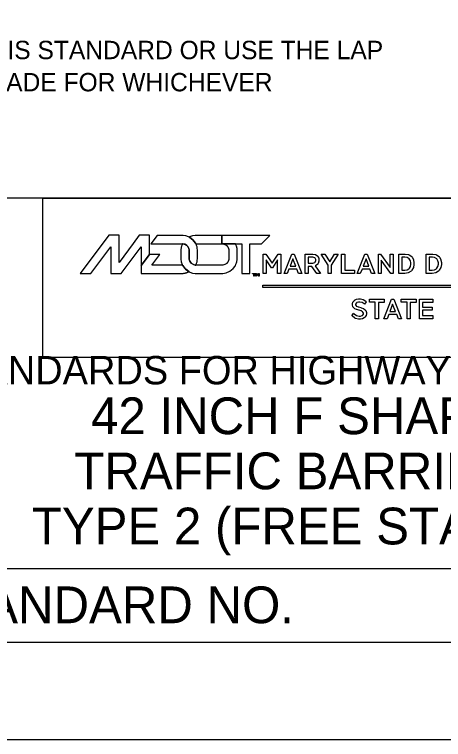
# Model space of a CAD drawing. Extents: x -27.4 to -18.9, y -4.2 to 6.8.
# Drawn here: x -23.046 to -21.647, y -4.191 to -1.823 of the extents above; entities that cross this region are included whole.
import ezdxf

# ---------------------------------------------------------------- set-up
doc = ezdxf.new("R2010")
doc.units = 0
for name, color, linetype in [('BORD-LINE', 7, 'Continuous'), ('Level 13', 7, 'Continuous'), ('MSHA-LOGO', 7, 'Continuous'), ('TTLB-TEXT', 7, 'Continuous'), ('USER-CLIP', 7, 'Continuous'), ('USER-LINE', 7, 'Continuous')]:
    doc.layers.add(name, color=color, linetype=linetype)

msp = doc.modelspace()

# ---------------------------------------------------------------- linework, layer by layer
at = {"layer": 'BORD-LINE'}
for p, q in [((-19.2324, -2.4232), (-23.7053, -2.4232)), ((-23.7053, -3.6322), (-19.2324, -3.6322))]:
    msp.add_line(p, q, dxfattribs=at)
msp.add_lwpolyline([(-26.6066, 6.4791), (-19.2324, 6.4791), (-19.2324, -3.874), (-26.6066, -3.874)], close=True, dxfattribs=at)
at = {"layer": 'MSHA-LOGO'}
for points in [[(-22.6334, -2.6432), (-22.6062, -2.607), (-22.6062, -2.5443), (-22.6392, -2.5443), (-22.6596, -2.5717), (-22.7055, -2.6329), (-22.7055, -2.5443), (-22.7384, -2.5443), (-22.8317, -2.6687), (-22.7977, -2.6687), (-22.7326, -2.5819), (-22.7326, -2.6687), (-22.6984, -2.6687), (-22.6334, -2.5819)], [(-22.4982, -2.5722), (-22.4974, -2.5723), (-22.4898, -2.5743), (-22.4891, -2.5747), (-22.4883, -2.5751), (-22.4845, -2.5778), (-22.4813, -2.5812), (-22.4807, -2.5819), (-22.4801, -2.5827), (-22.4779, -2.5874), (-22.4767, -2.5925), (-22.4766, -2.5936), (-22.4766, -2.5936), (-22.4766, -2.5938), (-22.4766, -2.5938), (-22.4766, -2.594), (-22.4766, -2.5946), (-22.4766, -2.5948), (-22.4766, -2.6184), (-22.4766, -2.6186), (-22.4766, -2.6192), (-22.4766, -2.6194), (-22.4766, -2.6194), (-22.4766, -2.6196), (-22.4766, -2.6196), (-22.4766, -2.6201), (-22.4768, -2.6213), (-22.4768, -2.6217), (-22.4765, -2.6236), (-22.4743, -2.6293), (-22.4696, -2.6355), (-22.4628, -2.64), (-22.4567, -2.6419), (-22.4554, -2.6419), (-22.4551, -2.6416), (-22.455, -2.6413), (-22.455, -2.6413), (-22.4548, -2.6409), (-22.4527, -2.6364), (-22.4526, -2.636), (-22.4524, -2.6355), (-22.451, -2.6308), (-22.4508, -2.6303), (-22.4508, -2.63), (-22.4502, -2.6276), (-22.4502, -2.6274), (-22.45, -2.6266), (-22.4493, -2.6203), (-22.4493, -2.6182), (-22.4493, -2.5951), (-22.4493, -2.5929), (-22.45, -2.5868), (-22.4502, -2.586), (-22.4502, -2.5858), (-22.4508, -2.5833), (-22.4508, -2.5831), (-22.451, -2.5826), (-22.4524, -2.5779), (-22.4526, -2.5774), (-22.4527, -2.5769), (-22.4548, -2.5725), (-22.455, -2.5721), (-22.4562, -2.5697), (-22.4641, -2.5595), (-22.4743, -2.5516), (-22.4766, -2.5504), (-22.4783, -2.5495), (-22.4875, -2.5463), (-22.4965, -2.5449), (-22.4994, -2.5449), (-22.5813, -2.5449), (-22.6018, -2.5721), (-22.4994, -2.5721), (-22.4994, -2.5721), (-22.4985, -2.5722)], [(-22.4548, -2.5724), (-22.4544, -2.5724), (-22.4541, -2.5724), (-22.3702, -2.5724), (-22.37, -2.5724), (-22.3697, -2.5724), (-22.3696, -2.5724), (-22.3695, -2.5721), (-22.3695, -2.545), (-22.3695, -2.545), (-22.37, -2.545), (-22.3702, -2.545), (-22.4541, -2.545), (-22.4571, -2.545), (-22.4661, -2.5465), (-22.4752, -2.5497), (-22.4766, -2.5504), (-22.4743, -2.5516), (-22.4641, -2.5595), (-22.4562, -2.5697), (-22.455, -2.5721)], [(-22.3695, -2.545), (-22.3695, -2.5722), (-22.3051, -2.5722), (-22.3051, -2.6687), (-22.2781, -2.6687), (-22.2781, -2.5722), (-22.2405, -2.5722), (-22.2136, -2.5452), (-22.2136, -2.545)], [(-22.4761, -2.6632), (-22.4762, -2.6632), (-22.4764, -2.663), (-22.4764, -2.663), (-22.4776, -2.6624), (-22.4879, -2.6548), (-22.4888, -2.6539), (-22.4897, -2.653), (-22.4971, -2.6428), (-22.4977, -2.6416), (-22.4979, -2.6416), (-22.4982, -2.6416), (-22.4982, -2.6416), (-22.4985, -2.6416), (-22.4992, -2.6416), (-22.4994, -2.6416), (-22.5989, -2.6416), (-22.5724, -2.6067), (-22.6064, -2.6067), (-22.6335, -2.6427), (-22.6335, -2.6689), (-22.4996, -2.6689), (-22.4988, -2.6689), (-22.4968, -2.6687), (-22.4965, -2.6687), (-22.4958, -2.6687), (-22.4939, -2.6684), (-22.4936, -2.6683), (-22.4934, -2.6683), (-22.4929, -2.6682), (-22.4927, -2.6682), (-22.4926, -2.6681), (-22.491, -2.6679), (-22.4909, -2.6678), (-22.4906, -2.6678), (-22.49, -2.6676), (-22.4898, -2.6676), (-22.4897, -2.6676), (-22.4882, -2.6673), (-22.4881, -2.6673), (-22.488, -2.6673), (-22.4872, -2.667), (-22.4871, -2.667), (-22.487, -2.6669), (-22.4857, -2.6665), (-22.4855, -2.6664), (-22.4855, -2.6664), (-22.4846, -2.6661), (-22.4845, -2.6661), (-22.4844, -2.6661), (-22.4831, -2.6656), (-22.483, -2.6656), (-22.4829, -2.6655), (-22.482, -2.6653), (-22.4819, -2.6652), (-22.4818, -2.6652), (-22.4803, -2.6646), (-22.4802, -2.6645), (-22.4801, -2.6645), (-22.4794, -2.6642), (-22.4794, -2.6642), (-22.4791, -2.6641), (-22.4771, -2.6631), (-22.477, -2.663), (-22.4768, -2.6631), (-22.4763, -2.6632)], [(-22.2353, -2.6056), (-22.2265, -2.6056), (-22.2062, -2.6352), (-22.1865, -2.6056), (-22.178, -2.6056), (-22.178, -2.669), (-22.1879, -2.669), (-22.1879, -2.625), (-22.2052, -2.6503), (-22.2078, -2.6503), (-22.2255, -2.625), (-22.2255, -2.669), (-22.2353, -2.669)], [(-22.1417, -2.6056), (-22.1342, -2.6056), (-22.1093, -2.669), (-22.1198, -2.669), (-22.1253, -2.6549), (-22.1512, -2.6549), (-22.1568, -2.669), (-22.1669, -2.669)], [(-22.1473, -2.6457), (-22.1286, -2.6457), (-22.1381, -2.6217)], [(-22.0979, -2.6694), (-22.0979, -2.6059), (-22.0756, -2.6059), (-22.0728, -2.6059), (-22.0653, -2.6073), (-22.0645, -2.6075), (-22.0637, -2.6078), (-22.058, -2.6116), (-22.0576, -2.6121), (-22.0572, -2.6126), (-22.0543, -2.6178), (-22.054, -2.6184), (-22.0538, -2.619), (-22.053, -2.6242), (-22.053, -2.6259), (-22.053, -2.6288), (-22.0557, -2.6366), (-22.0563, -2.6375), (-22.0569, -2.6383), (-22.0645, -2.644), (-22.0655, -2.6444), (-22.0484, -2.6697), (-22.0605, -2.6697), (-22.0759, -2.6463), (-22.088, -2.6463), (-22.088, -2.6697), (-22.0979, -2.6697)], [(-22.088, -2.6161), (-22.088, -2.6355), (-22.0753, -2.6355), (-22.0731, -2.6355), (-22.067, -2.6333), (-22.0664, -2.6328), (-22.0659, -2.6324), (-22.0632, -2.6271), (-22.0632, -2.6253), (-22.0632, -2.6236), (-22.0656, -2.6188), (-22.0661, -2.6184), (-22.0666, -2.618), (-22.0733, -2.6161), (-22.0756, -2.6161)], [(-22.0131, -2.6417), (-22.0131, -2.6694), (-22.0229, -2.6694), (-22.0229, -2.6417), (-22.0458, -2.6056), (-22.0337, -2.6056), (-22.018, -2.6309), (-22.002, -2.6056), (-21.9902, -2.6056)], [(-21.9791, -2.6056), (-21.9692, -2.6056), (-21.9692, -2.6588), (-21.9368, -2.6588), (-21.9368, -2.669), (-21.9791, -2.669)], [(-21.9031, -2.6056), (-21.8956, -2.6056), (-21.8707, -2.669), (-21.8812, -2.669), (-21.8868, -2.6549), (-21.9126, -2.6549), (-21.9182, -2.669), (-21.928, -2.669)], [(-21.9087, -2.6457), (-21.8901, -2.6457), (-21.8995, -2.6217)], [(-21.8184, -2.6694), (-21.8498, -2.6259), (-21.8498, -2.6694), (-21.8593, -2.6694), (-21.8593, -2.6059), (-21.8518, -2.6059), (-21.8203, -2.6493), (-21.8203, -2.6059), (-21.8108, -2.6059), (-21.8108, -2.6694)], [(-21.7928, -2.6056), (-21.7752, -2.6056), (-21.7714, -2.6056), (-21.7612, -2.6074), (-21.7601, -2.6078), (-21.7591, -2.6083), (-21.7506, -2.614), (-21.75, -2.6148), (-21.7494, -2.6155), (-21.745, -2.6237), (-21.7447, -2.6246), (-21.7445, -2.6255), (-21.7431, -2.6337), (-21.7431, -2.6365), (-21.7431, -2.6397), (-21.7451, -2.6495), (-21.7499, -2.6586), (-21.7513, -2.6602), (-21.7527, -2.6616), (-21.7616, -2.6668), (-21.7725, -2.669), (-21.7762, -2.669), (-21.7928, -2.669)], [(-21.783, -2.6161), (-21.783, -2.6588), (-21.7755, -2.6588), (-21.7731, -2.6588), (-21.7657, -2.6574), (-21.7597, -2.6539), (-21.7588, -2.6529), (-21.7579, -2.6519), (-21.7547, -2.6458), (-21.7533, -2.6388), (-21.7533, -2.6365), (-21.7533, -2.6342), (-21.7546, -2.6274), (-21.7587, -2.6209), (-21.7656, -2.617), (-21.7728, -2.6157), (-21.7752, -2.6157), (-21.783, -2.6157)], [(-21.7035, -2.6056), (-21.6858, -2.6056), (-21.6821, -2.6056), (-21.6719, -2.6074), (-21.6708, -2.6078), (-21.6697, -2.6083), (-21.6613, -2.614), (-21.6607, -2.6148), (-21.6601, -2.6155), (-21.6557, -2.6237), (-21.6554, -2.6246), (-21.6552, -2.6255), (-21.6538, -2.6337), (-21.6538, -2.6365), (-21.6538, -2.6397), (-21.6558, -2.6495), (-21.6606, -2.6586), (-21.6619, -2.6602), (-21.6633, -2.6616), (-21.6723, -2.6668), (-21.6832, -2.669), (-21.6868, -2.669), (-21.7035, -2.669)], [(-21.6934, -2.6161), (-21.6934, -2.6588), (-21.6858, -2.6588), (-21.6834, -2.6588), (-21.676, -2.6574), (-21.6701, -2.6539), (-21.6692, -2.6529), (-21.6683, -2.6519), (-21.665, -2.6458), (-21.6636, -2.6388), (-21.6636, -2.6365), (-21.6636, -2.6342), (-21.6649, -2.6274), (-21.669, -2.6209), (-21.6759, -2.617), (-21.6831, -2.6157), (-21.6855, -2.6157), (-21.6934, -2.6157)], [(-22.2695, -2.6687), (-22.2606, -2.6687), (-22.2606, -2.6703), (-22.2641, -2.6703), (-22.2641, -2.6776), (-22.2659, -2.6776), (-22.2659, -2.6703), (-22.2695, -2.6703)], [(-22.2594, -2.6687), (-22.2578, -2.6687), (-22.2539, -2.6731), (-22.2503, -2.6687), (-22.2487, -2.6687), (-22.2487, -2.6776), (-22.2507, -2.6776), (-22.2507, -2.6712), (-22.2541, -2.6753), (-22.2576, -2.6712), (-22.2576, -2.6776), (-22.2594, -2.6776)], [(-22.2362, -2.7073), (-20.1195, -2.7073), (-20.1195, -2.7152), (-22.2362, -2.7152)], [(-21.9101, -2.7946), (-21.9105, -2.7943), (-21.9147, -2.7916), (-21.9152, -2.7914), (-21.9158, -2.7912), (-21.9216, -2.7893), (-21.9223, -2.7891), (-21.9229, -2.789), (-21.9293, -2.7871), (-21.9299, -2.7869), (-21.9306, -2.7866), (-21.9364, -2.784), (-21.937, -2.7837), (-21.9375, -2.7833), (-21.9418, -2.7788), (-21.9421, -2.7782), (-21.9424, -2.7776), (-21.944, -2.7718), (-21.944, -2.7699), (-21.944, -2.7681), (-21.9424, -2.7628), (-21.9387, -2.7579), (-21.9376, -2.757), (-21.9366, -2.7561), (-21.9304, -2.7531), (-21.9236, -2.7519), (-21.9213, -2.7519), (-21.9181, -2.7519), (-21.9086, -2.7542), (-21.9003, -2.7597), (-21.899, -2.7612), (-21.9044, -2.7692), (-21.9056, -2.7681), (-21.9123, -2.7642), (-21.9193, -2.7625), (-21.9216, -2.7625), (-21.9238, -2.7625), (-21.9297, -2.7641), (-21.9303, -2.7644), (-21.9308, -2.7647), (-21.9338, -2.7688), (-21.9338, -2.7702), (-21.9338, -2.7715), (-21.9316, -2.7749), (-21.9312, -2.7753), (-21.9308, -2.7756), (-21.9252, -2.778), (-21.9245, -2.7782), (-21.9238, -2.7784), (-21.9167, -2.7805), (-21.9159, -2.7808), (-21.9151, -2.781), (-21.9079, -2.7837), (-21.9073, -2.784), (-21.9066, -2.7843), (-21.901, -2.7891), (-21.9005, -2.7898), (-21.9001, -2.7904), (-21.898, -2.7969), (-21.898, -2.7991), (-21.898, -2.801), (-21.8996, -2.8067), (-21.9033, -2.812), (-21.9044, -2.8129), (-21.9054, -2.8138), (-21.9115, -2.8169), (-21.9179, -2.8183), (-21.92, -2.8183), (-21.9237, -2.8183), (-21.9335, -2.8157), (-21.9347, -2.8151), (-21.9359, -2.8146), (-21.945, -2.8076), (-21.9456, -2.8068), (-21.9395, -2.7991), (-21.9383, -2.8006), (-21.9306, -2.806), (-21.922, -2.8084), (-21.9191, -2.8084), (-21.9171, -2.8084), (-21.9116, -2.8068), (-21.9111, -2.8065), (-21.9106, -2.8061), (-21.9082, -2.802), (-21.9082, -2.8007), (-21.9082, -2.7992), (-21.9098, -2.7949)], [(-21.8887, -2.7528), (-21.8402, -2.7528), (-21.8402, -2.7634), (-21.8593, -2.7634), (-21.8593, -2.8171), (-21.8692, -2.8171), (-21.8692, -2.7631), (-21.8884, -2.7631), (-21.8884, -2.7528)], [(-21.8162, -2.7528), (-21.8085, -2.7528), (-21.7833, -2.8171), (-21.7938, -2.8171), (-21.7993, -2.8029), (-21.8255, -2.8029), (-21.8309, -2.8171), (-21.8411, -2.8171)], [(-21.822, -2.7933), (-21.8031, -2.7933), (-21.8127, -2.7689)], [(-21.7849, -2.7528), (-21.7363, -2.7528), (-21.7363, -2.7634), (-21.7555, -2.7634), (-21.7555, -2.8171), (-21.7654, -2.8171), (-21.7654, -2.7631), (-21.7846, -2.7631), (-21.7846, -2.7528)], [(-21.7248, -2.7528), (-21.682, -2.7528), (-21.682, -2.7634), (-21.7149, -2.7634), (-21.7149, -2.7795), (-21.6842, -2.7795), (-21.6842, -2.7894), (-21.7149, -2.7894), (-21.7149, -2.8065), (-21.6814, -2.8065), (-21.6814, -2.8171), (-21.7248, -2.8171)]]:
    msp.add_lwpolyline(points, close=True, dxfattribs=at)
for points in [[(-22.4766, -2.6081), (-22.4766, -2.5951), (-22.4766, -2.5948), (-22.4766, -2.594), (-22.4766, -2.5938), (-22.4766, -2.5933), (-22.4764, -2.5921), (-22.4764, -2.5917), (-22.4766, -2.5908), (-22.4799, -2.5824), (-22.4804, -2.5817), (-22.4809, -2.5809), (-22.4842, -2.5775), (-22.4881, -2.5747), (-22.489, -2.5743), (-22.4897, -2.5739), (-22.4973, -2.5719), (-22.4981, -2.5719), (-22.4981, -2.572), (-22.4982, -2.5722), (-22.4986, -2.5729), (-22.5013, -2.5796), (-22.5015, -2.5803), (-22.5016, -2.5806), (-22.5023, -2.583), (-22.5024, -2.5833), (-22.5026, -2.5842), (-22.5037, -2.5924), (-22.5037, -2.5951), (-22.5037, -2.6081), (-22.5037, -2.6094)], [(-22.3199, -2.5951), (-22.3199, -2.5944), (-22.32, -2.5925), (-22.32, -2.5922), (-22.32, -2.5921), (-22.32, -2.5914), (-22.32, -2.5908), (-22.3202, -2.5897), (-22.3202, -2.5893), (-22.3202, -2.5892), (-22.3202, -2.5889), (-22.3202, -2.5888), (-22.3202, -2.5887), (-22.3202, -2.5885), (-22.3202, -2.5884), (-22.3202, -2.5883), (-22.3205, -2.5865), (-22.3205, -2.5864), (-22.3205, -2.5862), (-22.3207, -2.5858), (-22.3207, -2.5857), (-22.3208, -2.5855), (-22.3212, -2.5836), (-22.3212, -2.5834), (-22.3212, -2.5833), (-22.3212, -2.5831), (-22.3213, -2.5828), (-22.322, -2.5802), (-22.3221, -2.58), (-22.3222, -2.5796), (-22.3238, -2.5753), (-22.324, -2.5748), (-22.3241, -2.5746), (-22.3251, -2.5725), (-22.3252, -2.5722), (-22.3252, -2.5722), (-22.3253, -2.5719), (-22.3688, -2.5719), (-22.369, -2.5722), (-22.3684, -2.5722), (-22.3683, -2.5722), (-22.368, -2.5722), (-22.3675, -2.5724), (-22.3674, -2.5724), (-22.3671, -2.5725), (-22.3636, -2.5731), (-22.3633, -2.5733), (-22.363, -2.5734), (-22.3602, -2.5743), (-22.3598, -2.5745), (-22.3597, -2.5746), (-22.3581, -2.5754), (-22.358, -2.5755), (-22.3578, -2.5755), (-22.3578, -2.5755), (-22.3577, -2.5756), (-22.3562, -2.5765), (-22.3561, -2.5766), (-22.3559, -2.5767), (-22.3559, -2.5767), (-22.3558, -2.5768), (-22.3545, -2.5778), (-22.3544, -2.5779), (-22.3542, -2.5781), (-22.3541, -2.5782), (-22.3531, -2.5792), (-22.353, -2.5793), (-22.3529, -2.5795), (-22.3528, -2.5795), (-22.3526, -2.5796), (-22.3526, -2.5797), (-22.3518, -2.5806), (-22.3518, -2.5807), (-22.3516, -2.5809), (-22.3516, -2.5809), (-22.3513, -2.5813), (-22.3513, -2.5814), (-22.3512, -2.5815), (-22.3505, -2.5825), (-22.3504, -2.5826), (-22.3504, -2.5826), (-22.3501, -2.5832), (-22.3501, -2.5833), (-22.3499, -2.5834), (-22.3499, -2.5834), (-22.3499, -2.5835), (-22.3494, -2.5844), (-22.3494, -2.5845), (-22.3493, -2.5846), (-22.3491, -2.5852), (-22.349, -2.5853), (-22.349, -2.5854), (-22.3486, -2.5864), (-22.3485, -2.5865), (-22.3485, -2.5866), (-22.3484, -2.5872), (-22.3484, -2.5873), (-22.3482, -2.5875), (-22.3482, -2.5876), (-22.3481, -2.5876), (-22.3478, -2.5884), (-22.3478, -2.5886), (-22.3478, -2.5887), (-22.3475, -2.5897), (-22.3475, -2.5898), (-22.3475, -2.5901), (-22.3473, -2.5906), (-22.3473, -2.5908), (-22.3473, -2.591), (-22.3472, -2.5919), (-22.3472, -2.5922), (-22.3472, -2.5924), (-22.347, -2.5929), (-22.347, -2.5931), (-22.347, -2.5936), (-22.3468, -2.5949), (-22.3468, -2.5953), (-22.3468, -2.6189), (-22.3468, -2.6195), (-22.3469, -2.621), (-22.347, -2.6211), (-22.347, -2.6214), (-22.3471, -2.6219), (-22.3472, -2.622), (-22.3472, -2.6223), (-22.3473, -2.6231), (-22.3473, -2.6234), (-22.3473, -2.6236), (-22.3475, -2.6242), (-22.3475, -2.6244), (-22.3475, -2.6245), (-22.3478, -2.6255), (-22.3478, -2.6256), (-22.3479, -2.6257), (-22.3481, -2.6266), (-22.3482, -2.6267), (-22.3482, -2.6267), (-22.3483, -2.627), (-22.3484, -2.627), (-22.3485, -2.6275), (-22.3485, -2.6277), (-22.3486, -2.6278), (-22.349, -2.6288), (-22.349, -2.6289), (-22.3491, -2.629), (-22.3493, -2.6297), (-22.3494, -2.6298), (-22.3494, -2.6298), (-22.3499, -2.6307), (-22.3499, -2.6308), (-22.35, -2.631), (-22.3501, -2.631), (-22.3501, -2.631), (-22.3504, -2.6316), (-22.3504, -2.6317), (-22.3505, -2.6317), (-22.3512, -2.6328), (-22.3513, -2.6329), (-22.3513, -2.6329), (-22.3516, -2.6333), (-22.3516, -2.6334), (-22.3518, -2.6336), (-22.3519, -2.6336), (-22.3526, -2.6345), (-22.3526, -2.6346), (-22.3528, -2.6348), (-22.3529, -2.6349), (-22.353, -2.6349), (-22.3531, -2.635), (-22.3541, -2.636), (-22.3542, -2.6361), (-22.3544, -2.6363), (-22.3545, -2.6364), (-22.3558, -2.6374), (-22.3559, -2.6375), (-22.3561, -2.6376), (-22.3561, -2.6377), (-22.3562, -2.6378), (-22.3576, -2.6386), (-22.3578, -2.6387), (-22.3579, -2.6387), (-22.358, -2.6387), (-22.3581, -2.6388), (-22.3597, -2.6397), (-22.3598, -2.6397), (-22.3601, -2.6399), (-22.363, -2.6409), (-22.3633, -2.641), (-22.3636, -2.641), (-22.3671, -2.6418), (-22.3674, -2.6418), (-22.3676, -2.6418), (-22.3682, -2.6419), (-22.3683, -2.642), (-22.3686, -2.642), (-22.3692, -2.642), (-22.3695, -2.642), (-22.4534, -2.642), (-22.4537, -2.642), (-22.4544, -2.642), (-22.4546, -2.642), (-22.4567, -2.6419), (-22.4628, -2.64), (-22.4696, -2.6353), (-22.4742, -2.6286), (-22.4761, -2.6225), (-22.4763, -2.6205), (-22.4763, -2.6201), (-22.4763, -2.6193), (-22.4763, -2.6191), (-22.4763, -2.6081), (-22.4766, -2.6081)], [(-22.5037, -2.6094), (-22.5037, -2.6191), (-22.5037, -2.6221), (-22.5023, -2.6311), (-22.4991, -2.6403), (-22.4982, -2.642), (-22.4976, -2.6432), (-22.49, -2.6536), (-22.4891, -2.6546), (-22.4882, -2.6555), (-22.4778, -2.6631), (-22.4766, -2.6637), (-22.4749, -2.6646), (-22.4657, -2.6678), (-22.4568, -2.6692), (-22.4538, -2.6692), (-22.3698, -2.6692), (-22.3663, -2.6692), (-22.3559, -2.6672), (-22.3435, -2.6617), (-22.3331, -2.6531), (-22.3269, -2.645), (-22.3253, -2.642), (-22.3252, -2.6418), (-22.3242, -2.6396), (-22.3241, -2.6394), (-22.324, -2.639), (-22.3224, -2.6347), (-22.3223, -2.6342), (-22.3222, -2.634), (-22.3214, -2.6314), (-22.3214, -2.6311), (-22.3214, -2.631), (-22.3214, -2.6308), (-22.3214, -2.6306), (-22.3209, -2.6287), (-22.3209, -2.6286), (-22.3209, -2.6284), (-22.3207, -2.628), (-22.3207, -2.6279), (-22.3207, -2.6277), (-22.3204, -2.626), (-22.3204, -2.6258), (-22.3204, -2.6257), (-22.3204, -2.6255), (-22.3204, -2.6255), (-22.3204, -2.6253), (-22.3204, -2.625), (-22.3204, -2.6249), (-22.3204, -2.6244), (-22.3202, -2.6233), (-22.3202, -2.6229), (-22.3202, -2.6222), (-22.3202, -2.622), (-22.3202, -2.6213), (-22.32, -2.6196), (-22.32, -2.6191), (-22.3199, -2.5951)]]:
    msp.add_lwpolyline(points, dxfattribs=at)
at = {"layer": 'USER-CLIP'}
msp.add_lwpolyline([(-18.9155, 6.8091), (-27.4155, 6.8091), (-27.4155, -4.1909), (-18.9155, -4.1909)], close=True, dxfattribs=at)
at = {"layer": 'USER-LINE'}
msp.add_lwpolyline([(-19.9833, -2.9439), (-22.9545, -2.9439), (-22.9545, -2.4232), (-19.9833, -2.4232)], close=True, dxfattribs=at)

# ---------------------------------------------------------------- texts
at = {"layer": 'Level 13'}
for s, height, p in [('10. THE CONTRACTOR MAY CONSTRUCT THE VERTICAL NO. 5 BARS AS SHOWN ON THIS STANDARD OR USE THE LAP', 0.06, (-26.4754, -1.9693)), ('    SPLICE SHOWN ON STD. NO. MD 648.55. NO ADDITIONAL COMPENSATION WILL BE MADE FOR WHICHEVER', 0.06, (-26.4754, -2.0743)), ('42 INCH F SHAPE CONCRETE', 0.120019, (-22.7966, -3.1938)), ('TRAFFIC BARRIER SINGLE FACE', 0.120019, (-22.8513, -3.3738)), ('TYPE 2 (FREE STANDING IN FILL)', 0.120019, (-22.99, -3.5538))]:
    msp.add_text(s, height=height, dxfattribs=at).set_placement(p)
at = {"layer": 'TTLB-TEXT'}
for s, height, p in [('STANDARDS FOR HIGHWAYS AND INCIDENTAL STRUCTURES', 0.09269, (-23.3095, -3.0312)), ('STANDARD NO.', 0.12, (-23.3471, -3.8111))]:
    msp.add_text(s, height=height, dxfattribs=at).set_placement(p)

doc.saveas('drawing.dxf')
